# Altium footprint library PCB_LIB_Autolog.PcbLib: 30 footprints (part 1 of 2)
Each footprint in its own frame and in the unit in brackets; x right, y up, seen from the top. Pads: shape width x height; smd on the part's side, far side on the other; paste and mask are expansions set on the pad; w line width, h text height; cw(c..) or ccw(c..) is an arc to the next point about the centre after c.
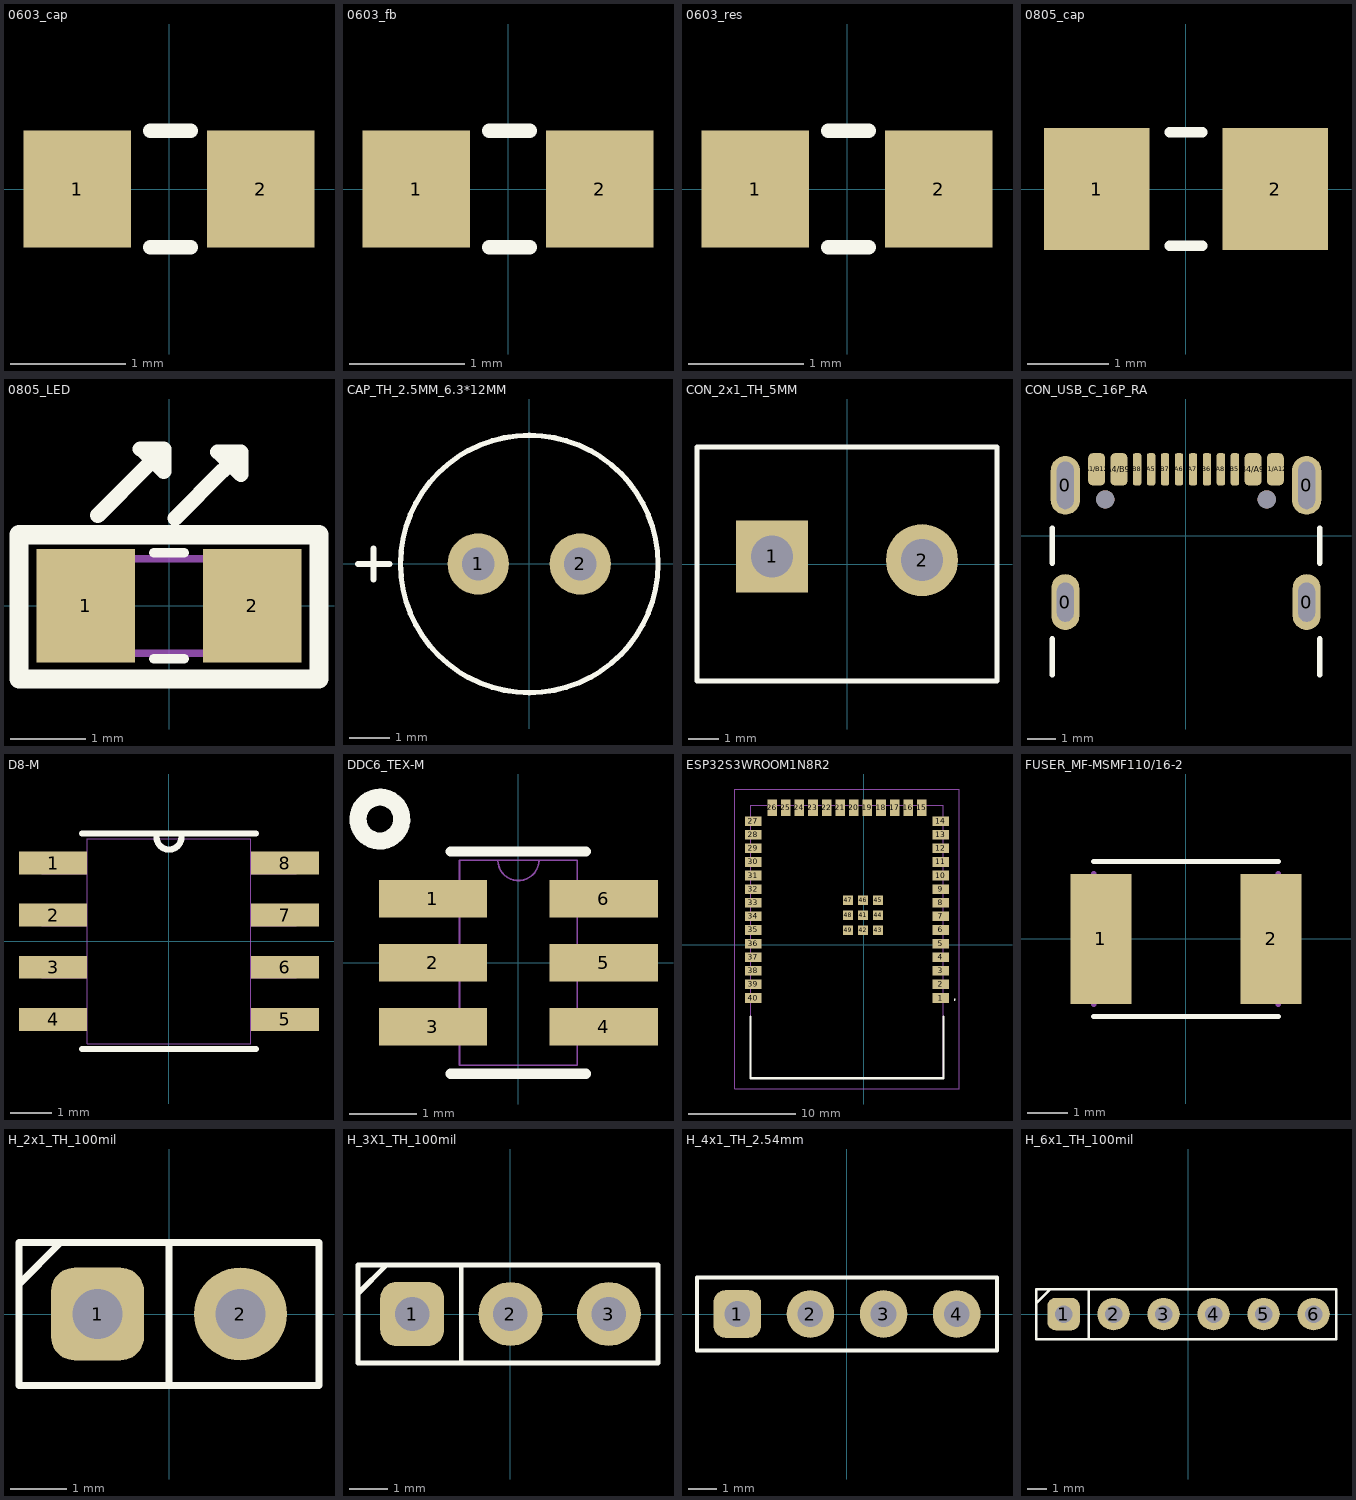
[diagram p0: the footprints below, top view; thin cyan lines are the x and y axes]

## 0603_cap [mil]
pads (2):
  rect 37x40 smd: 1(-31.5,0) 2(31.5,0)
Top Overlay:
  lines w5: -6.5,-20 7.5,-20 ; -6.5,20 7.5,20
3D body "CircuitWorks-CAPACITOR 0603.STEP": height 34.36, standoff 0.5, extent -31.5,-16.93 31.5,16.93

## 0603_fb [mil]
pads (2):
  rect 37x40 smd: 1(-31.5,0) 2(31.5,0)
Top Overlay:
  lines w5: -6.5,-20 7.5,-20 ; -6.5,20 7.5,20
3D body "742792602.stp": height 32, standoff 0.5, extent -31.5,-15.75 31.49,15.75

## 0603_res [mil] "1608 Metric / 20190225 / C-A.Serna.A"
pads (2):
  rect 37x40 smd: 1(-31.5,0) 2(31.5,0)
Top Overlay:
  lines w5: -6.5,-20 7.5,-20 ; -6.5,20 7.5,20
3D body "C0603.step": height 11.89, standoff 0, extent -31.5,-15.75 31.5,15.75

## 0805_cap [mm]
pads (2):
  rect 1.3x1.5 smd: 1(-1.1,0) 2(1.1,0)
Top Overlay:
  lines w0.127: -0.2,-0.7 0.2,-0.7 ; -0.2,0.7 0.2,0.7
3D body: height 1, standoff 0, extent -1.125,-0.7 1.075,0.7

## 0805_LED [mm]
pads (2):
  rect 1.3x1.5 smd: 1(-1.1,0) 2(1.1,0)
Top Overlay:
  lines w0.127: -0.2,-0.7 0.2,-0.7 ; -0.2,0.7 0.2,0.7
  lines w0.203: -0.941,1.197 -0.306,1.832 ; -0.38,2.072 -0.069,2.072 -0.069,1.775 -0.366,2.072 ; 0.079,1.157 0.714,1.792 ; 0.64,2.032 0.951,2.032 0.951,1.735 0.654,2.032
  lines w0.254: -1.981,-0.965 1.981,-0.965 1.981,0.94 -1.981,0.94 -1.981,-0.965
Mechanical 1:
  lines w0.1: -0.7,-0.625 -0.7,0.625 ; 0.7,-0.625 0.7,0.625 ; -1,-0.625 1,-0.625 1,0.625 -1,0.625 -1,-0.625
3D body: height 1.1, standoff 0.5, extent -0.7,-0.625 0.7,0.625
3D body: height 0.5, standoff 0, extent -1,-0.625 1,0.625

## CAP_TH_2.5MM_6.3*12MM [mm]
pads (2):
  round 1.5 hole 0.8: 1(-1.25,0) 2(1.25,0)
Top Overlay:
  circle w0.127: c0,0 r3.15
  lines w0.152: -4.191,0 -3.429,0 ; -3.81,-0.381 -3.81,0.381
3D body: height 12, standoff 0, extent -3.15,-3.15 3.15,3.15

## CON_2x1_TH_5MM [mm]
pads (2):
  rect 2.4x2.4 hole 1.4: 1(-2.5,0.254)
  round 2.4 hole 1.4: 2(2.5,0.127)
Top Overlay:
  lines w0.152: -5,-3.9 -5,3.9 5,3.9 5,-3.9 -5,-3.9
3D body: height 10.2, standoff 0, extent -5,-3.9 5,3.9

## CON_USB_C_16P_RA [mm]
pads (18):
  oval 1x2 hole 0.6 slot 1.4 at 90 deg: 0(-4.32,-2.377) 0(4.32,-2.377)
  oval 1.05x2.1 hole 0.6 slot 1.7 at 90 deg: 0(-4.32,1.803) 0(4.32,1.803)
  rrect50% 0.6x1.15 smd: A1/B12(-3.2,2.378) A4/B9(-2.4,2.378) B1/A12(3.2,2.378) B4/A9(2.4,2.378)
  rrect50% 0.3x1.15 smd: A5(-1.25,2.378) A6(-0.25,2.378) A7(0.25,2.378) A8(1.25,2.378) B5(1.75,2.378) B6(0.75,2.378) B7(-0.75,2.378) B8(-1.75,2.378)
  round 0.65 hole 0.65 unplated: ""(-2.89,1.303) ""(2.89,1.303)
Top Overlay:
  lines w0.2: -4.79,-4.977 -4.79,-3.697 ; -4.79,-0.977 -4.79,0.273 ; 4.79,-4.977 4.79,-3.697 ; 4.79,-0.977 4.79,0.273
3D body "step_temp.STEP": height 3.31, standoff -0.85, extent -4.79,-4.977 4.79,2.733

## D8-M [mil]
pads (8):
  rect 65.5x22 smd paste+0: 1(-111.25,75) 2(-111.25,25) 3(-111.25,-25) 4(-111.25,-75) 5(111.25,-75) 6(111.25,-25) 7(111.25,25) 8(111.25,75)
Top Overlay:
  lines w6: -83.5,-103.5 83.5,-103.5 ; -83.5,103.5 83.5,103.5 ; -12,100 ccw(c0,100) 12,100
Mechanical 13:
  lines w1: -12,98.5 ccw(c0,98.5) 12,98.5 ; -122,-85 -78.5,-85 -78.5,-65 -122,-65 -122,-85 ; -122,-35 -78.5,-35 -78.5,-15 -122,-15 -122,-35 ; -122,15 -78.5,15 -78.5,35 -122,35 -122,15 ; -122,65 -78.5,65 -78.5,85 -122,85 -122,65 ; -78.5,-98.5 -78.5,98.5 78.5,98.5 78.5,-98.5 -78.5,-98.5 ; 78.5,-85 122,-85 122,-65 78.5,-65 78.5,-85 ; 78.5,-35 122,-35 122,-15 78.5,-15 78.5,-35 ; 78.5,15 122,15 122,35 78.5,35 78.5,15 ; 78.5,65 122,65 122,85 78.5,85 78.5,65
3D body "D8.step": height 69.09, standoff 0, extent -122.01,-98.5 122.01,98.5

## DDC6_TEX-M [mm]
pads (6):
  rect 1.61x0.558 smd paste+0: 1(-1.269,0.95) 2(-1.269,0) 3(-1.269,-0.95) 4(1.269,-0.95) 5(1.269,0) 6(1.269,0.95)
Top Overlay:
  lines w0.152: -1.003,-1.651 1.003,-1.651 ; -1.003,1.651 1.003,1.651
  lines w0.254: -1.751,2.243 ccw(c-2.057,2.134) -1.745,2.223
Mechanical 13:
  lines w0.025: -0.305,1.524 ccw(c0,1.524) 0.305,1.524 ; -1.524,-1.204 -0.876,-1.204 -0.876,-0.696 -1.524,-0.696 -1.524,-1.204 ; -1.524,-0.254 -0.876,-0.254 -0.876,0.254 -1.524,0.254 -1.524,-0.254 ; -1.524,0.696 -0.876,0.696 -0.876,1.204 -1.524,1.204 -1.524,0.696 ; -0.876,-1.524 -0.876,1.524 0.876,1.524 0.876,-1.524 -0.876,-1.524 ; 0.876,-1.204 1.524,-1.204 1.524,-0.696 0.876,-0.696 0.876,-1.204 ; 0.876,-0.254 1.524,-0.254 1.524,0.254 0.876,0.254 0.876,-0.254 ; 0.876,0.696 1.524,0.696 1.524,1.204 0.876,1.204 0.876,0.696
3D body "DDC6_TEX.step": height 1.7, standoff 0, extent -1.524,-1.524 1.524,1.524

## ESP32S3WROOM1N8R2 [mm]
pads (49):
  rect 1.5x0.9 smd: 1(7.201,-4.955) 2(7.201,-3.685) 3(7.201,-2.415) 4(7.201,-1.145) 5(7.201,0.125) 6(7.201,1.395) 7(7.201,2.665) 8(7.201,3.935) 9(7.201,5.205) 10(7.201,6.475) 11(7.201,7.745) 12(7.201,9.015) 13(7.201,10.285) 14(7.201,11.555) 27(-10.299,11.555) 28(-10.299,10.285) 29(-10.299,9.015) 30(-10.299,7.745) 31(-10.299,6.475) 32(-10.299,5.205) 33(-10.299,3.935) 34(-10.299,2.665) 35(-10.299,1.395) 36(-10.299,0.125) 37(-10.299,-1.145) 38(-10.299,-2.415) 39(-10.299,-3.685) 40(-10.299,-4.955)
  rect 0.9x1.5 smd: 15(5.436,12.805) 16(4.166,12.805) 17(2.896,12.805) 18(1.626,12.805) 19(0.356,12.805) 20(-0.914,12.805) 21(-2.184,12.805) 22(-3.454,12.805) 23(-4.724,12.805) 24(-5.994,12.805) 25(-7.264,12.805) 26(-8.534,12.805)
  rect 0.9x0.9 smd: 41(-0.049,2.765) 42(-0.049,1.365) 43(1.351,1.365) 44(1.351,2.765) 45(1.351,4.165) 46(-0.049,4.165) 47(-1.449,4.165) 48(-1.449,2.765) 49(-1.449,1.365)
Top Overlay:
  lines w0.1: 8.451,-5.095 ccw(c8.501,-5.095) 8.551,-5.095 ccw(c8.501,-5.095) 8.451,-5.095
  lines w0.2: -10.549,-6.695 -10.549,-12.445 7.451,-12.445 7.451,-6.695
Mechanical 13:
  lines w0.1: -12.049,-13.445 8.951,-13.445 8.951,14.555 -12.049,14.555 -12.049,-13.445 ; -10.549,-12.445 7.451,-12.445 7.451,13.055 -10.549,13.055 -10.549,-12.445
3D body "step_temp.STEP": height 3.25, standoff 0, extent -10.549,-12.445 7.451,13.055

## FUSER_MF-MSMF110/16-2 [mm]
pads (2):
  rect 1.5x3.2 smd: 1(-2.1,0) 2(2.1,0)
Top Overlay:
  lines w0.127: -2.275,-1.913 2.275,-1.913 ; -2.275,1.913 2.275,1.913
Mechanical 13:
  lines w0.127: -2.275,-1.62 -2.275,1.62 ; 2.275,-1.62 2.275,1.62
3D body "step_temp.STEP": height 0.85, standoff 0, extent -2.275,-1.62 2.275,1.62

## H_2x1_TH_100mil [mil]
pads (2):
  rrect50% 65x65 hole 35: 1(-50,0)
  round 65 hole 35: 2(50,0)
Top Overlay:
  lines w5: -105,20.87 -75.87,50 ; 0,-50 0,50 ; -105,-50 105,-50 105,50 -105,50 -105,-50
3D body "PH1-02-UA.STEP": height 338.58, standoff -116.14, extent -100.8,-49.16 99.48,49.26

## H_3X1_TH_100mil [mil]
pads (3):
  rrect50% 65x65 hole 35: 1(-100,0)
  round 65 hole 35: 2(0,0) 3(100,0)
Top Overlay:
  lines w5: -155,20.87 -125.87,50 ; -50,-50 -50,50 ; -155,-50 150,-50 150,50 -155,50 -155,-50
3D body "5-146278-3--3DModel-STEP-1.STEP": height 320.5, standoff -119.5, extent -142,-46 142,46

## H_4x1_TH_2.54mm [mil]
pads (4):
  rrect50% 65x65 hole 35: 1(-150,0)
  round 65 hole 35: 2(-50,0) 3(50,0) 4(150,0)
Top Overlay:
  lines w5: -205,-50 205.12,-50 205.12,50 -205,50 -205,-50
3D body "TSW-104-14-T-S.step": height 420, standoff -110, extent -200.01,-50 204.99,50

## H_6x1_TH_100mil [mil]
pads (6):
  rrect50% 65x65 hole 35: 1(-250,0)
  round 65 hole 35: 2(-150,0) 3(-50,0) 4(50,0) 5(150,0) 6(250,0)
Top Overlay:
  lines w5: -305,20.87 -275.87,50 ; -200,-50 -200,50 ; -305,-50 295,-50 295,50 -305,50 -305,-50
